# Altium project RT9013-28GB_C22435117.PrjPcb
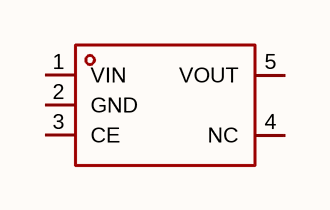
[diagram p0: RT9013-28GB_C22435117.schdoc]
1 sheet, 1 parts. Net scope: global (net labels, ports and power ports of the same name join across sheets).

## Sheet RT9013-28GB_C22435117.schdoc
size 127 x 101 mm

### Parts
U?  rt9013-28gb_c22435117  [SOT-23-5_L3.0-W1.7-P0.95-LS2.8-BR]  (value not drawn)

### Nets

Not connected (* = marked no-connect by the designer): U? 1(VIN) 2(GND) 3(CE) 4(NC) 5(VOUT)

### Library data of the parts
U? = rt9013-28gb_c22435117: 输出极性:正极;工作电压:7V;输出电压:2.8V;输出电流:500mA;电源纹波抑制比(PSRR):70dB@(1kHz);输出类型:固定;; Manufacturer: TECH PUBLIC(台舟); AddInBom: yes; ModelId: 0a2a1b8f50944f73965918ad6e5fe167; ModelName: SOT-23-5_L2.9-W1.6-H1.1-LS2.8-P0.95; ModelTransform: 114.173,109.636,0,180,0,0,0,0,0; Output Configuration: 正极; Voltage - Supply: 7V; Output Voltage: 2.8V; Output Current: 500mA; Voltage Dropout: 100mV@(100mA)；300mV@(200mA); standby current: 60uA; Noise: 50uVrms; Output Type: 固定; Number of Outputs: 1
